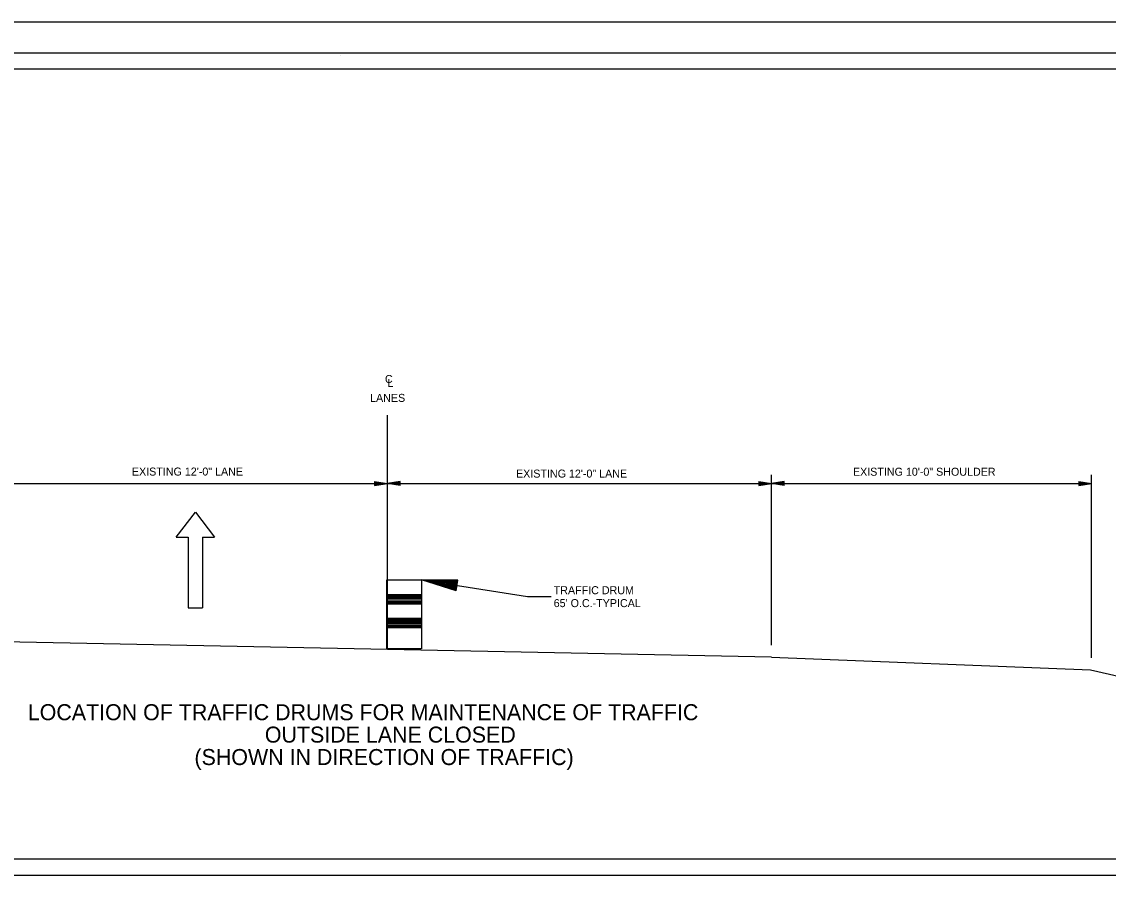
# Model space of a CAD drawing. Extents: x 13528 to 25043, y 7635 to 10612.
# Drawn here: x 20354 to 21033, y 10073 to 10612 of the extents above; entities that cross this region are included whole.
import ezdxf

# ---------------------------------------------------------------- set-up
doc = ezdxf.new("R2010")
doc.units = 0
for name, color, linetype in [('Default', 7, 'Continuous'), ('R_Border', 7, 'Continuous'), ('R_Border Plan-Plan', 7, 'Continuous'), ('R_Draft', 7, 'Continuous'), ('R_Revision Date Text', 7, 'Continuous'), ('STAMP_PE_TAEGTMEYER-SIGNATURE', 7, 'Continuous')]:
    doc.layers.add(name, color=color, linetype=linetype)

msp = doc.modelspace()

# ---------------------------------------------------------------- linework, layer by layer
at = {"layer": 'Default'}
for p, q in [((20582.81, 10219.42), (20582.81, 10365.75)), ((20822.86, 10313.48), (20822.86, 10328.58)), ((21022.89, 10315), (21022.89, 10328.58)), ((20342.76, 10323.08), (20582.81, 10323.08)), ((20572.15, 10323.08), (20582.81, 10323.08)), ((20574.81, 10324.28), (20582.81, 10323.08)), ((20574.81, 10324.28), (20574.81, 10321.88)), ((20574.81, 10324.08), (20581.47, 10323.08)), ((20574.81, 10323.88), (20580.09, 10323.08)), ((20574.81, 10323.68), (20578.77, 10323.08)), ((20574.81, 10323.48), (20577.41, 10323.08)), ((20574.81, 10323.28), (20576.07, 10323.08)), ((20574.81, 10321.88), (20582.81, 10323.08)), ((20574.81, 10322.7), (20577.41, 10323.08)), ((20574.81, 10322.28), (20580.09, 10323.08)), ((20574.81, 10322.08), (20581.47, 10323.08)), ((20574.81, 10322.48), (20578.77, 10323.08)), ((20574.81, 10322.9), (20576.07, 10323.08)), ((20590.81, 10324.28), (20582.81, 10323.08)), ((20582.81, 10323.08), (20822.86, 10323.08)), ((20590.81, 10321.88), (20582.81, 10323.08)), ((20590.81, 10324.08), (20584.15, 10323.08)), ((20590.81, 10322.08), (20584.15, 10323.08)), ((20590.81, 10323.88), (20585.53, 10323.08)), ((20590.81, 10322.28), (20585.53, 10323.08)), ((20590.81, 10323.68), (20586.85, 10323.08)), ((20590.81, 10322.48), (20586.85, 10323.08)), ((20590.81, 10323.48), (20588.21, 10323.08)), ((20590.81, 10322.7), (20588.21, 10323.08)), ((20590.81, 10323.28), (20589.55, 10323.08)), ((20590.81, 10322.9), (20589.55, 10323.08)), ((20590.81, 10321.88), (20590.81, 10324.28)), ((20814.85, 10324.28), (20822.86, 10323.08)), ((20814.85, 10324.28), (20814.85, 10321.88)), ((20814.85, 10324.08), (20821.51, 10323.08)), ((20814.85, 10323.88), (20820.13, 10323.08)), ((20814.85, 10323.68), (20818.81, 10323.08)), ((20814.85, 10323.48), (20817.45, 10323.08)), ((20814.85, 10323.28), (20816.11, 10323.08)), ((20814.85, 10321.88), (20822.86, 10323.08)), ((20814.85, 10322.7), (20817.45, 10323.08)), ((20814.85, 10322.28), (20820.13, 10323.08)), ((20814.85, 10322.08), (20821.51, 10323.08)), ((20814.85, 10322.48), (20818.81, 10323.08)), ((20814.85, 10322.9), (20816.11, 10323.08)), ((20830.86, 10324.28), (20822.86, 10323.08)), ((20822.86, 10323.08), (21022.89, 10323.08)), ((20830.86, 10321.88), (20822.86, 10323.08)), ((20830.86, 10324.08), (20824.2, 10323.08)), ((20830.86, 10322.08), (20824.2, 10323.08)), ((20830.86, 10323.88), (20825.58, 10323.08)), ((20830.86, 10322.28), (20825.58, 10323.08)), ((20830.86, 10323.68), (20826.9, 10323.08)), ((20830.86, 10322.48), (20826.9, 10323.08)), ((20830.86, 10323.48), (20828.26, 10323.08)), ((20830.86, 10322.7), (20828.26, 10323.08)), ((20830.86, 10323.28), (20829.6, 10323.08)), ((20830.86, 10322.9), (20829.6, 10323.08)), ((20830.86, 10321.88), (20830.86, 10324.28)), ((21014.89, 10324.28), (21022.89, 10323.08)), ((21014.89, 10324.28), (21014.89, 10321.88)), ((21014.89, 10324.08), (21021.55, 10323.08)), ((21014.89, 10323.88), (21020.17, 10323.08)), ((21014.89, 10323.68), (21018.85, 10323.08)), ((21014.89, 10323.48), (21017.49, 10323.08)), ((21014.89, 10323.28), (21016.15, 10323.08)), ((21014.89, 10321.88), (21022.89, 10323.08)), ((21014.89, 10322.7), (21017.49, 10323.08)), ((21014.89, 10322.28), (21020.17, 10323.08)), ((21014.89, 10322.08), (21021.55, 10323.08)), ((21014.89, 10322.48), (21018.85, 10323.08)), ((21014.89, 10322.9), (21016.15, 10323.08)), ((21022.89, 10214.24), (21022.89, 10315)), ((20822.86, 10222.22), (20822.86, 10313.48)), ((20604.14, 10262.97), (20670.41, 10252.54)), ((20670.41, 10252.54), (20685.19, 10252.54)), ((20582.81, 10219.42), (20342.76, 10224.22)), ((20822.86, 10214.62), (20582.81, 10219.42)), ((20822.86, 10214.62), (21022.13, 10206.66)), ((21022.13, 10206.66), (21175.72, 10172.25))]:
    msp.add_line(p, q, dxfattribs=at)
at = {"layer": 'R_Border'}
for p, q in [((20625.84, 10256.14), (20604.14, 10262.97)), ((20626.89, 10262.81), (20604.14, 10262.97)), ((20625.93, 10256.7), (20607.85, 10262.39)), ((20626.81, 10262.25), (20607.85, 10262.39)), ((20626.72, 10261.69), (20611.67, 10261.79)), ((20626.02, 10257.26), (20611.67, 10261.79)), ((20626.11, 10257.82), (20615.38, 10261.2)), ((20626.63, 10261.13), (20615.38, 10261.2)), ((20626.54, 10260.56), (20619.14, 10260.61)), ((20626.2, 10258.4), (20619.14, 10260.61)), ((20625.84, 10256.14), (20626.89, 10262.81)), ((20582.53, 10253.72), (20604.14, 10253.72)), ((20626.45, 10260), (20622.86, 10260.03)), ((20626.29, 10258.95), (20622.86, 10260.03)), ((20582.53, 10252.92), (20604.14, 10252.92)), ((20582.53, 10252.13), (20604.14, 10252.13)), ((20582.53, 10251.42), (20604.14, 10251.42)), ((20582.53, 10250.55), (20604.14, 10250.55)), ((20582.53, 10249.5), (20604.14, 10249.5)), ((20582.53, 10248.51), (20604.14, 10248.51)), ((20582.53, 10247.91), (20604.14, 10247.91)), ((20582.53, 10238.91), (20604.14, 10238.91)), ((20582.53, 10238.11), (20604.14, 10238.11)), ((20582.53, 10237.32), (20604.14, 10237.32)), ((20582.53, 10236.61), (20604.14, 10236.61)), ((20582.53, 10235.74), (20604.14, 10235.74)), ((20582.53, 10234.69), (20604.14, 10234.69)), ((20582.53, 10233.7), (20604.14, 10233.7)), ((20582.53, 10233.1), (20604.14, 10233.1))]:
    msp.add_line(p, q, dxfattribs=at)
msp.add_lwpolyline([(20582.53, 10262.97), (20604.14, 10262.97), (20604.14, 10219.76), (20582.53, 10219.76)], close=True, dxfattribs=at)
at = {"layer": 'R_Border Plan-Plan'}
msp.add_line((19790.89, 10078.42), (21371.79, 10078.42), dxfattribs=at)
at = {"layer": 'R_Draft'}
for p, q in [((19790.89, 10592.07), (21371.79, 10592.07)), ((20553.49, 10590.77), (20553.49, 10590.77)), ((20553.49, 10590.77), (20553.49, 10590.77))]:
    msp.add_line(p, q, dxfattribs=at)
at = {"layer": 'R_Revision Date Text'}
for points in [[(19728.86, 10611.55), (21395.56, 10611.55), (21395.56, 9544.86), (19728.86, 9544.86)], [(21361.79, 10088.42), (19800.89, 10088.42), (19800.89, 10582.07), (21048.59, 10582.07), (21048.59, 10532.67), (21136.29, 10532.67), (21256.79, 10532.67), (21256.79, 10421.01), (21361.79, 10421.01)], [(19800.89, 10582.07), (21048.59, 10582.07), (21048.59, 10532.67), (21136.29, 10532.67), (21256.79, 10532.67), (21256.79, 10421.01), (21361.79, 10421.01), (21361.79, 9574.77), (19800.89, 9574.77)]]:
    msp.add_lwpolyline(points, close=True, dxfattribs=at)
at = {"layer": 'STAMP_PE_TAEGTMEYER-SIGNATURE'}
for p, q in [((20450.78, 10289.67), (20462.78, 10305.25)), ((20462.78, 10305.25), (20474.79, 10289.67)), ((20450.78, 10289.67), (20458.28, 10289.67)), ((20458.28, 10289.67), (20458.28, 10245.52)), ((20467.28, 10289.67), (20467.28, 10245.52)), ((20467.28, 10289.67), (20474.79, 10289.67)), ((20458.28, 10245.52), (20467.28, 10245.52))]:
    msp.add_line(p, q, dxfattribs=at)

# ---------------------------------------------------------------- texts
at = {"layer": 'Default'}
for s, height, p in [('C', 5, (20581.26, 10385.89)), ('L', 5, (20582.81, 10383.37)), ('LANES', 5.001, (20571.98, 10374.1)), ('EXISTING 12\'-0" LANE', 5.001, (20423.13, 10328.07)), ('EXISTING 12\'-0" LANE', 5.001, (20663.18, 10326.81)), ('EXISTING 10\'-0" SHOULDER', 5.001, (20873.75, 10327.97)), ('LOCATION OF TRAFFIC DRUMS FOR MAINTENANCE OF TRAFFIC', 10.002, (20358.06, 10175.27)), ('OUTSIDE LANE CLOSED', 10.002, (20506.2, 10161.27)), ('(SHOWN IN DIRECTION OF TRAFFIC)', 10.002, (20462.21, 10147.26))]:
    msp.add_text(s, height=height, dxfattribs=at).set_placement(p)
for s, p in [('TRAFFIC DRUM', (20686.73, 10253.96)), ("65' O.C.-TYPICAL", (20686.73, 10245.91))]:
    msp.add_text(s, height=5.001, rotation=360, dxfattribs=at).set_placement(p)

doc.saveas('drawing.dxf')
